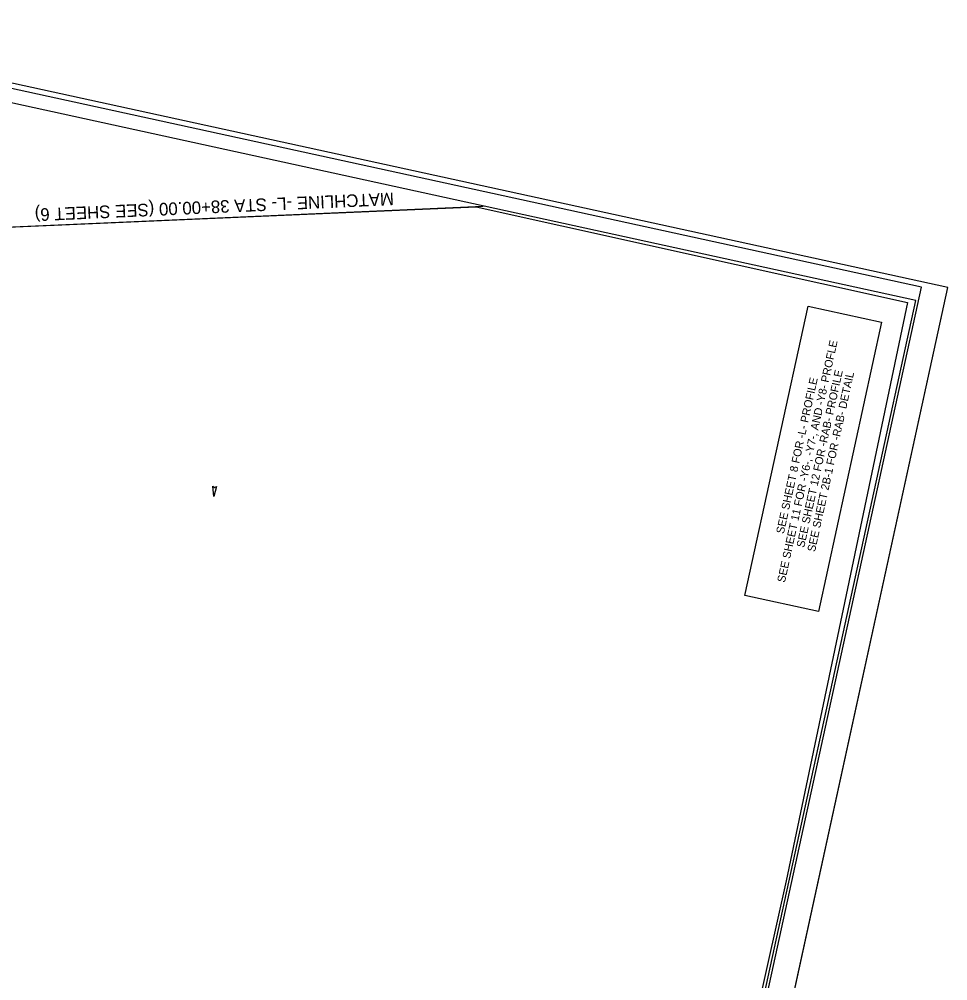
# Model space of a CAD drawing. Extents: x 1615716 to 1617263, y 900664 to 902742.
# Drawn here: x 1616451 to 1617263, y 901703 to 902544 of the extents above; entities that cross this region are included whole.
import ezdxf

# ---------------------------------------------------------------- set-up
doc = ezdxf.new("R2010")
doc.units = 0
for name, color, linetype in [('Prop CMT Slope Cut', 7, 'Continuous'), ('Prop Drainage Structure Plot Symbol 20 Scale', 7, 'Continuous'), ('Prop Plan Preparation Crest Label', 7, 'Continuous'), ('Prop SS Cut Line', 7, 'Continuous'), ('Prop SS Cut Text', 7, 'Continuous'), ('Prop SS Fill Line', 7, 'Continuous'), ('Prop SS Fill Text', 7, 'Continuous'), ('Scratch_Level_0', 7, 'Continuous'), ('Scratch_Level_3', 7, 'Continuous')]:
    doc.layers.add(name, color=color, linetype=linetype)

msp = doc.modelspace()

# ---------------------------------------------------------------- linework, layer by layer
at = {"layer": 'Prop Drainage Structure Plot Symbol 20 Scale'}
msp.add_lwpolyline([(1616850.42, 902379.94), (1617227.49, 902296.2), (1617121.36, 901790.43), (1617088.18, 901641.75), (1617042.44, 901522.26), (1617032.35, 901430.63), (1617021.35, 901334.38), (1616928.77, 900896.77), (1615902.83, 901120.28), (1615974.27, 901386.7), (1616087.67, 901888.92), (1616145.49, 901879.24), (1616184.12, 901827.49), (1616138.37, 901614.97), (1616150.59, 901618.07), (1616181.32, 901620.66), (1616299.19, 901764.2), (1616120.07, 901933.32), (1616161.35, 902112.51), (1616179.69, 902310.42), (1616338.57, 902281.41), (1616353.46, 902358.26)], close=True, dxfattribs=at)
at = {"layer": 'Prop Plan Preparation Crest Label'}
msp.add_lwpolyline([(1617085.33, 902040.02), (1617140.55, 902293), (1617204.78, 902278.98), (1617149.56, 902026)], close=True, dxfattribs=at)
at = {"layer": 'Prop SS Cut Line'}
msp.add_line((1616903.54, 900663.99), (1617262.68, 902309.25), dxfattribs=at)
at = {"layer": 'Prop SS Cut Text'}
msp.add_lwpolyline([(1616208.96, 902534.66), (1615853.55, 900906.5), (1616884.38, 900681.48), (1617239.79, 902309.64)], close=True, dxfattribs=at)
at = {"layer": 'Prop SS Fill Line'}
msp.add_lwpolyline([(1616208.79, 902521.9), (1615888.89, 901056.41), (1616914.73, 900832.48), (1617234.63, 902297.97)], close=True, dxfattribs=at)
at = {"layer": 'Prop SS Fill Text'}
msp.add_lwpolyline([(1616187.99, 902543.84), (1615828.85, 900898.58), (1616903.54, 900663.99), (1617262.68, 902309.25)], close=True, dxfattribs=at)
at = {"layer": 'Scratch_Level_0'}
msp.add_line((1616350.65, 902358.04), (1616856.51, 902380.51), dxfattribs=at)
at = {"layer": 'Scratch_Level_3'}
msp.add_lwpolyline([(1616623.17, 902135.32), (1616620.88, 902126.48), (1616620.03, 902135.63), (1616621.53, 902134.35)], close=True, dxfattribs=at)
msp.add_lwpolyline([(1616623.17, 902135.32), (1616620.88, 902126.48), (1616620.03, 902135.63), (1616621.53, 902134.35)], close=True, dxfattribs=at)

# ---------------------------------------------------------------- texts
at = {"layer": 'Prop CMT Slope Cut'}
msp.add_text('MATCHLINE -L- STA 38+00.00 (SEE SHEET 6)', height=11, rotation=182.58128, dxfattribs=at).set_placement((1616778.17, 902392.37))
at = {"layer": 'Prop Plan Preparation Crest Label'}
for s, p in [('SEE SHEET 11 FOR -Y6-, -Y7-, AND -Y8- PROFLE', (1617120.27, 902050.97)), ('SEE SHEET 12 FOR -RAB- PROFILE', (1617137.16, 902081.49)), ('SEE SHEET 8 FOR -L- PROFILE', (1617119.34, 902093.58)), ('SEE SHEET 2B-1 FOR -RAB- DETAIL', (1617146.58, 902077.74))]:
    msp.add_text(s, height=7, rotation=77.68623, dxfattribs=at).set_placement(p)

doc.saveas('drawing.dxf')
